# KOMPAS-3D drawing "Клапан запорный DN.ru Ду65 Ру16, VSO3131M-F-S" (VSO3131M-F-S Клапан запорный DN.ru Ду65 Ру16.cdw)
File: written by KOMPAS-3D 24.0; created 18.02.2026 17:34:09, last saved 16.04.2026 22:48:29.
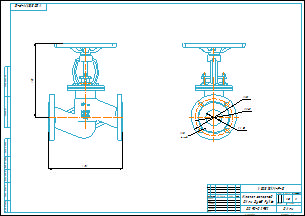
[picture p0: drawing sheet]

Document properties: Автор: R2D2; Форматы листов документа: A2; Полное имя файла: VSO3131M-F-S Клапан запорный DN.ru Ду65 Ру16.m3d; Масса: 16; Наименование: Клапан запорный DN.ru Ду65 Ру16; Количество листов документа: 1; Примечание: D090-02952

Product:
- Component [detail]: Корпус  | qty 1  | pos. 1  | Масса: 6.9; Автор: R2D2; source file: исходные материалы\Корпус.m3d
- Component [detail]: Клапан запорный DN.ru Ду65 Ру16  | designation VSO1121M-F-S  | qty 1  | pos. 2  | Масса: 19.42; Раздел спецификации: Прочие изделия; Примечание: D090-01948; Автор: R2D2; source file: исходные материалы\2.m3d
- Component [standard]: Hexagon head screw ISO 4017 - М10 x 20  | qty 4  | Масса: 0.023019; Раздел спецификации: Стандартные изделия; Рассекать на разрезах: no
- Part/product: Клапан запорный DN.ru Ду65 Ру16  | designation VSO3131M-F-S
    Масса: 16
    Раздел спецификации: Прочие изделия
    Примечание: D090-02952

Views: Вид 1, Спереди, Проекционный вид 2
Referenced files in E:\Работа\Зайцев\VSO3131M-F-S Клапан запорный DN.ru Ду15-100 Ру40\DN50\: VSO3131M-F-S Клапан запорный DN.ru Ду50 Ру40.m3d
Referenced files in E:\Работа\Зайцев\VSO3131M-F-S Клапан запорный DN.ru Ду15-100 Ру16\DN65\: VSO3131M-F-S Клапан запорный DN.ru Ду65 Ру16.m3d
Referenced files in E:\Работа\Зайцев\Для компаса\: чертеж DN.ru А3.cdt
Referenced files in E:\Работа\Зайцев\VSO3131M-F-S Клапан запорный DN.ru Ду15-100 Ру16\DN65\исходные материалы\: Корпус.m3d, 2.m3d
Referenced files in C:\Program Files\ASCON\KOMPAS-3D v24\Libs\PolynomLib\DATA\vault\Methods\Kompas\3D\: PLib_Bolt_1_ISO_1100.m3d
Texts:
  Линейный размер
  VSO3131M-F-S
  Диаметральный размер
  чертеж DN.ru А3.cdt
  Клапан запорный
  DN.ru Ду65 Ру16
  Труба
  Колонна
  Ребро жесткости
  ОТЛИВКА
  ЛЕЙБЛ
  Фланец верх
  Фланец
  отвертие во фланце
  Труба / Нестандартная труба / L = 148.6 мм
  Труба Нестандартная труба L = 148.6 мм
  Корпус
  Клапан запорный DN.ru Ду65 Ру16
  VSO1121M-F-S
  VSO1121M-F-S Клапан запорный DN.ru Ду65 Ру16
  Hexagon head screw ISO 4017 - М10 x 20
  VSO3131M-F-S Клапан запорный DN.ru Ду65 Ру16
Dimensions and other numbers on the sheet: 0; 3; 2; 4; 290; 180; 145; 65; 18; 4 отв.; 1:2; 1; 16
